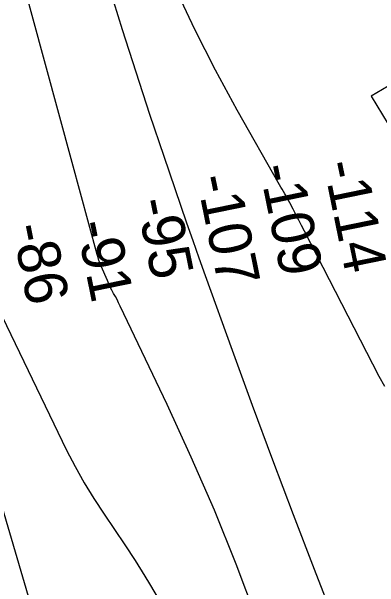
# Model space of a CAD drawing. Extents: x 3625074 to 3663148, y 511451 to 537151.
# Drawn here: x 3632455 to 3633034, y 526871 to 527777 of the extents above; entities that cross this region are included whole.
import ezdxf

# ---------------------------------------------------------------- set-up
doc = ezdxf.new("R2010")
doc.units = 0
for name, color, linetype in [('V-RIVR-RANG', 7, 'Continuous'), ('V-RRAP-RVMT', 7, 'Continuous'), ('V-TOPO-MAJR', 7, 'Continuous'), ('V-TOPO-MINR', 7, 'Continuous')]:
    doc.layers.add(name, color=color, linetype=linetype)

msp = doc.modelspace()

# ---------------------------------------------------------------- linework, layer by layer
at = {"layer": 'V-RRAP-RVMT'}
for p, q in [((3633097.49, 527689.13), (3633020.94, 527643.22)), ((3633020.94, 527643.22), (3633077.01, 527549.75))]:
    msp.add_line(p, q, dxfattribs=at)
at = {"layer": 'V-TOPO-MAJR'}
msp.add_lwpolyline([(3633055.2, 526580.81), (3632931.6, 526899.65), (3632898.7, 526985.37), (3632866.18, 527071.23), (3632834.24, 527157.3), (3632802.68, 527243.52), (3632760.08, 527361.15), (3632750.19, 527388.69), (3632740.39, 527416.26), (3632730.74, 527443.89), (3632721.19, 527471.55), (3632694.86, 527548.46), (3632672.55, 527614.71), (3632650.69, 527681.11), (3632629.48, 527747.71), (3632608.72, 527814.46)], dxfattribs=at)
at = {"layer": 'V-TOPO-MINR'}
for points in [[(3632181.11, 528160.54), (3632388.13, 527428.71), (3632392.05, 527415.34), (3632396.15, 527402.02), (3632400.5, 527388.79), (3632405.02, 527375.61), (3632409.89, 527362.56), (3632415.04, 527349.62), (3632420.62, 527336.87), (3632426.48, 527324.24), (3632541.48, 527087), (3632554.82, 527061.07), (3632568.96, 527035.61), (3632584.31, 527010.86), (3632600.45, 526986.58), (3632616.99, 526962.52), (3632633.26, 526938.28), (3632649.12, 526913.77), (3632664.71, 526889.08), (3632672.13, 526877.1), (3632690.17, 526845.79)], [(3632840.47, 526822.78), (3632808.06, 526908.01), (3632774.03, 526992.57), (3632737.58, 527076.12), (3632699.52, 527158.98), (3632625.81, 527313.56), (3632623.34, 527318.6), (3632620.81, 527323.62), (3632618.18, 527328.58), (3632615.48, 527333.51), (3632612.82, 527338.45), (3632610.26, 527343.44), (3632607.86, 527348.52), (3632605.57, 527353.64), (3632595.92, 527376.16), (3632594.08, 527380.71), (3632592.38, 527385.29), (3632590.87, 527389.95), (3632589.49, 527394.65), (3632550.34, 527539.32), (3632529.42, 527616.37), (3632508.41, 527693.39), (3632487.26, 527770.38), (3632466.02, 527847.34)], [(3633042.15, 527187.06), (3633033.18, 527202.78), (3632915.65, 527431.39), (3632911.21, 527440.03), (3632906.77, 527448.67), (3632902.32, 527457.31), (3632897.88, 527465.96), (3632892.7, 527476.05), (3632890.8, 527479.62), (3632888.86, 527483.16), (3632886.82, 527486.65), (3632884.73, 527490.11), (3632882.62, 527493.56), (3632880.54, 527497.03), (3632878.49, 527500.52), (3632876.48, 527504.02), (3632809.78, 527621.67), (3632775.66, 527684.6), (3632743.16, 527748.32), (3632713.08, 527813.22)], [(3632166.49, 527805.67), (3632182.76, 527767.78), (3632208.48, 527707.78), (3632233.59, 527646.72), (3632257.5, 527585.2), (3632279.59, 527523.01), (3632300.47, 527460.37), (3632330.29, 527366.32), (3632335.29, 527350.35), (3632340.24, 527334.37), (3632345.08, 527318.35), (3632349.85, 527302.31), (3632494.99, 526809.36), (3632513.47, 526746.62), (3632531.96, 526683.88), (3632550.47, 526621.15), (3632569, 526558.42), (3632598.71, 526457.85), (3632602.25, 526445.38), (3632605.61, 526432.86), (3632608.71, 526420.27), (3632611.63, 526407.63), (3632786.39, 525611.96)]]:
    msp.add_lwpolyline(points, dxfattribs=at)

# ---------------------------------------------------------------- texts
at = {"layer": 'V-RIVR-RANG'}
for s, p in [('-114', (3632945, 527537.56)), ('-109', (3632844.02, 527532.26)), ('-107', (3632745.41, 527515.33)), ('-95', (3632650.87, 527478.5)), ('-91', (3632555.96, 527443.48)), ('-86', (3632454.93, 527438.43))]:
    msp.add_text(s, height=67, rotation=281.54678, dxfattribs=at).set_placement(p)

doc.saveas('drawing.dxf')
